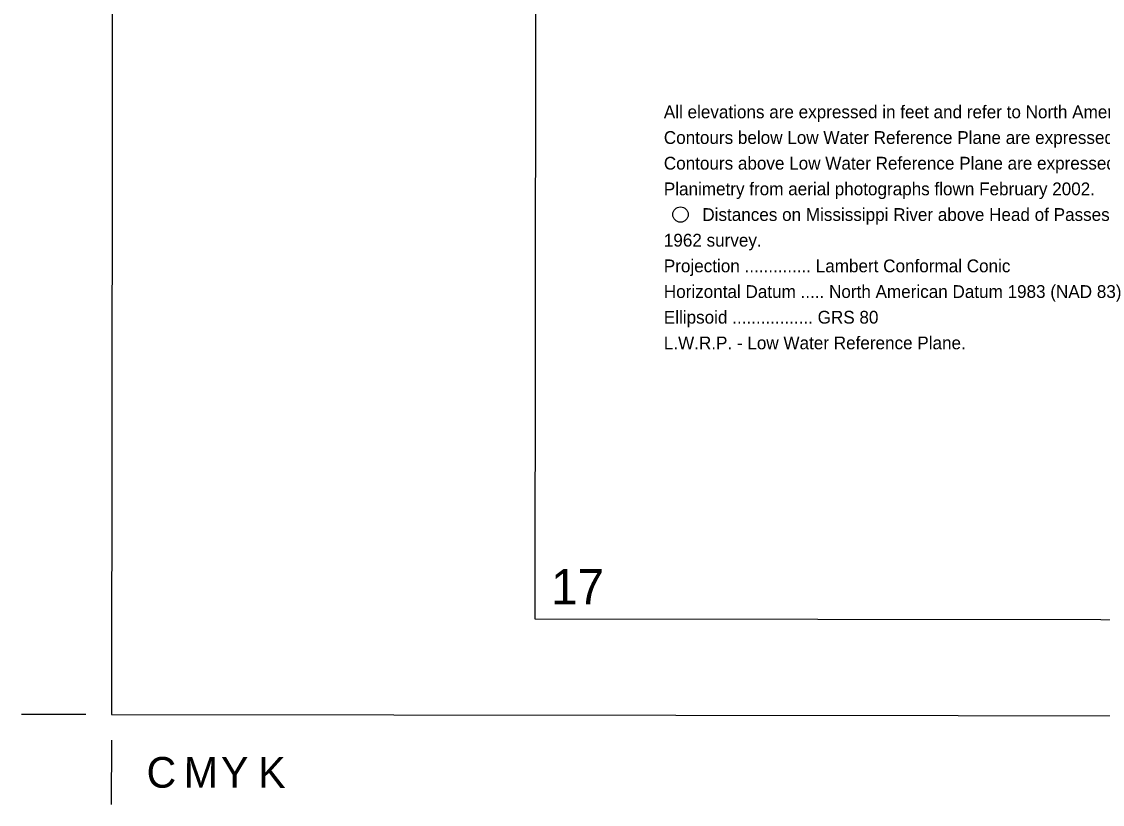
# Model space of a CAD drawing. Extents: x 3219052 to 3256913, y 800770 to 826146.
# Drawn here: x 3219052 to 3226073, y 800813 to 805896 of the extents above; entities that cross this region are included whole.
import ezdxf

# ---------------------------------------------------------------- set-up
doc = ezdxf.new("R2010")
doc.units = 0
for name, color, linetype in [('G-ANNO-NPLT', 7, 'Continuous'), ('V-ANNO-DIMS', 7, 'Continuous'), ('V-ANNO-NOTE', 7, 'Continuous'), ('V-ANNO-SYMB', 7, 'Continuous'), ('V-ANNO-TEXT', 7, 'Continuous')]:
    doc.layers.add(name, color=color, linetype=linetype)

msp = doc.modelspace()

# ---------------------------------------------------------------- linework, layer by layer
at = {"layer": 'G-ANNO-NPLT'}
msp.add_lwpolyline([(3219635.1, 801396), (3256301.7, 801353.3), (3256329.8, 825519.9), (3219663.2, 825562.6)], close=True, dxfattribs=at)
at = {"layer": 'V-ANNO-DIMS'}
for p, q in [((3219468.4, 801396.2), (3219051.7, 801396.6)), ((3219634.9, 801229.3), (3219634.4, 800812.6))]:
    msp.add_line(p, q, dxfattribs=at)
at = {"layer": 'V-ANNO-NOTE'}
msp.add_circle((3223332.1, 804643), 50, dxfattribs=at)
at = {"layer": 'V-ANNO-SYMB'}
msp.add_lwpolyline([(3222385.9, 802017.8), (3255469.1, 801979.3), (3255495.8, 824895.9), (3222412.6, 824934.4), (3222385.9, 802017.8)], dxfattribs=at)

# ---------------------------------------------------------------- texts
at = {"layer": 'V-ANNO-DIMS'}
for s, p in [('C', (3219863.5, 800921.1)), ('M', (3220105.2, 800920.8)), ('Y', (3220346.8, 800920.5)), ('K', (3220588.5, 800920.2))]:
    msp.add_text(s, height=199.3, rotation=359.93333, dxfattribs=at).set_placement(p)
at = {"layer": 'V-ANNO-NOTE'}
for s, rotation, p in [('All elevations are expressed in feet and refer to North American Vertical Datum of 1988.', 0.00001, (3223223.9, 805268.3)), ('Contours below Low Water Reference Plane are expressed in feet at 5 and 10 ft. intervals.', 0.00001, (3223223.9, 805101.6)), ('Contours above Low Water Reference Plane are expressed in feet at 5 ft. intervals.', 0.00001, (3223223.9, 804934.9)), ('Planimetry from aerial photographs flown February 2002.', 0.00001, (3223223.9, 804768.2)), ('Distances on Mississippi River above Head of Passes are shown at 1 mile intervals,', 0.00001, (3223474.1, 804601.5)), ('1962 survey.', 0.00001, (3223223.9, 804434.8)), ('Projection .............. Lambert Conformal Conic', 359.99998, (3223223.9, 804268.1)), ('Horizontal Datum ..... North American Datum 1983 (NAD 83)', 359.99998, (3223223.9, 804101.4)), ('Ellipsoid ................. GRS 80', 359.99998, (3223223.9, 803934.7)), ('L.W.R.P. - Low Water Reference Plane.', 359.99998, (3223223.9, 803768))]:
    msp.add_text(s, height=83, rotation=rotation, dxfattribs=at).set_placement(p)
at = {"layer": 'V-ANNO-TEXT'}
msp.add_text('17', height=230, rotation=359.93332, dxfattribs=at).set_placement((3222492.2, 802111))

doc.saveas('drawing.dxf')
